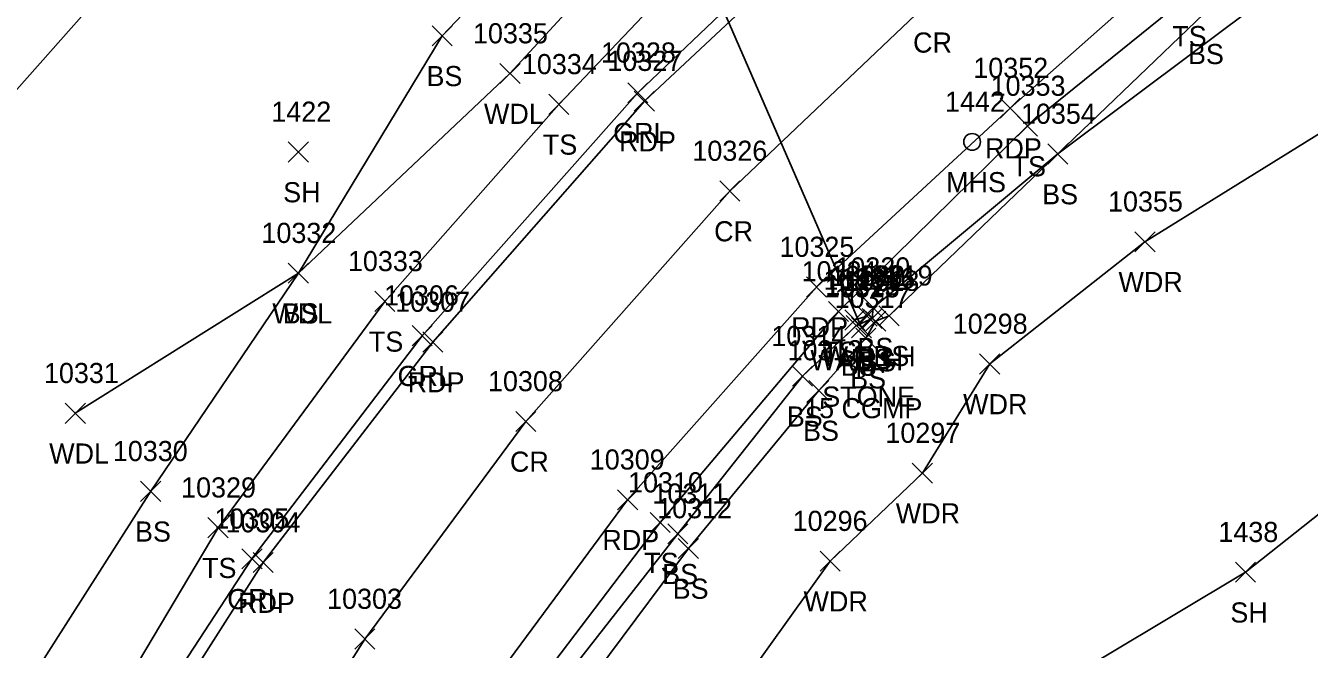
# Model space of a CAD drawing. Extents: x 1651685 to 1653558, y 889533 to 891085.
# Drawn here: x 1652813.1 to 1652940.5, y 890590.1 to 890652 of the extents above; entities that cross this region are included whole.
import ezdxf

# ---------------------------------------------------------------- set-up
doc = ezdxf.new("R2010")
doc.units = 0
for name, color, linetype in [('D_A', 7, 'Continuous'), ('D_C', 7, 'Continuous'), ('D_I', 7, 'Continuous'), ('D_TIC', 7, 'Continuous'), ('DCP', 7, 'Continuous'), ('DHW', 7, 'Continuous'), ('L_A', 7, 'Continuous'), ('L_I', 7, 'Continuous'), ('L_TIC', 7, 'Continuous'), ('LAWA', 7, 'Continuous'), ('LELB', 7, 'Continuous'), ('LSOGP', 7, 'Continuous'), ('P_A', 7, 'Continuous'), ('P_I', 7, 'Continuous'), ('P_TIC', 7, 'Continuous'), ('PET', 7, 'Continuous'), ('PRC', 7, 'Continuous'), ('R_A', 7, 'Continuous'), ('R_I', 7, 'Continuous'), ('R_TIC', 7, 'Continuous'), ('RGR', 7, 'Continuous'), ('U_A', 7, 'Continuous'), ('U_I', 7, 'Continuous'), ('USMH', 7, 'Continuous')]:
    doc.layers.add(name, color=color, linetype=linetype)

msp = doc.modelspace()

# ---------------------------------------------------------------- linework, layer by layer
at = {"layer": 'D_TIC'}
for points in [[(1652895.63, 890622.2), (1652897.63, 890624.2)], [(1652897.63, 890622.2), (1652895.63, 890624.2)], [(1652894.4, 890621.81), (1652896.4, 890623.81)], [(1652896.4, 890621.81), (1652894.4, 890623.81)], [(1652895.07, 890621.05), (1652897.07, 890623.05)], [(1652897.07, 890621.05), (1652895.07, 890623.05)]]:
    msp.add_lwpolyline(points, dxfattribs=at)
at = {"layer": 'DCP'}
msp.add_lwpolyline([(1652896.07, 890622.05), (1652875.51, 890669.35)], dxfattribs=at)
at = {"layer": 'DHW'}
msp.add_lwpolyline([(1652895.4, 890622.81), (1652896.63, 890623.2)], dxfattribs=at)
at = {"layer": 'L_TIC'}
for points in [[(1652853.42, 890650.04), (1652855.42, 890652.04)], [(1652855.42, 890650.04), (1652853.42, 890652.04)], [(1652860.15, 890646.29), (1652862.15, 890648.29)], [(1652862.15, 890646.29), (1652860.15, 890648.29)], [(1652865.01, 890643.23), (1652867.01, 890645.23)], [(1652867.01, 890643.23), (1652865.01, 890645.23)], [(1652911.56, 890641.08), (1652913.56, 890643.08)], [(1652913.56, 890641.08), (1652911.56, 890643.08)], [(1652839.14, 890638.5), (1652841.14, 890640.5)], [(1652841.14, 890638.5), (1652839.14, 890640.5)], [(1652914.57, 890638.3), (1652916.57, 890640.3)], [(1652916.57, 890638.3), (1652914.57, 890640.3)], [(1652914.57, 890638.3), (1652916.57, 890640.3)], [(1652916.57, 890638.3), (1652914.57, 890640.3)], [(1652923.22, 890629.58), (1652925.22, 890631.58)], [(1652925.22, 890629.58), (1652923.22, 890631.58)], [(1652839.14, 890626.46), (1652841.14, 890628.46)], [(1652841.14, 890626.46), (1652839.14, 890628.46)], [(1652839.14, 890626.46), (1652841.14, 890628.46)], [(1652841.14, 890626.46), (1652839.14, 890628.46)], [(1652847.73, 890623.66), (1652849.73, 890625.66)], [(1652849.73, 890623.66), (1652847.73, 890625.66)], [(1652892.78, 890622.65), (1652894.78, 890624.65)], [(1652894.78, 890622.65), (1652892.78, 890624.65)], [(1652896.22, 890623.03), (1652898.22, 890625.03)], [(1652898.22, 890623.03), (1652896.22, 890625.03)], [(1652897.8, 890622.23), (1652899.8, 890624.23)], [(1652899.8, 890622.23), (1652897.8, 890624.23)], [(1652894.56, 890621.27), (1652896.56, 890623.27)], [(1652896.56, 890621.27), (1652894.56, 890623.27)], [(1652896.12, 890621.95), (1652898.12, 890623.95)], [(1652898.12, 890621.95), (1652896.12, 890623.95)], [(1652896.47, 890621.7), (1652898.47, 890623.7)], [(1652898.47, 890621.7), (1652896.47, 890623.7)], [(1652895.5, 890620.01), (1652897.5, 890622.01)], [(1652897.5, 890620.01), (1652895.5, 890622.01)], [(1652907.8, 890617.44), (1652909.8, 890619.44)], [(1652909.8, 890617.44), (1652907.8, 890619.44)], [(1652889.21, 890616.22), (1652891.21, 890618.22)], [(1652891.21, 890616.22), (1652889.21, 890618.22)], [(1652890.82, 890614.8), (1652892.82, 890616.8)], [(1652892.82, 890614.8), (1652890.82, 890616.8)], [(1652816.98, 890612.54), (1652818.98, 890614.54)], [(1652818.98, 890612.54), (1652816.98, 890614.54)], [(1652901.11, 890606.6), (1652903.11, 890608.6)], [(1652903.11, 890606.6), (1652901.11, 890608.6)], [(1652824.47, 890604.79), (1652826.47, 890606.79)], [(1652826.47, 890604.79), (1652824.47, 890606.79)], [(1652831.16, 890601.17), (1652833.16, 890603.17)], [(1652833.16, 890601.17), (1652831.16, 890603.17)], [(1652875.07, 890601.68), (1652877.07, 890603.68)], [(1652877.07, 890601.68), (1652875.07, 890603.68)], [(1652876.83, 890600.57), (1652878.83, 890602.57)], [(1652878.83, 890600.57), (1652876.83, 890602.57)], [(1652877.87, 890599.11), (1652879.87, 890601.11)], [(1652879.87, 890599.11), (1652877.87, 890601.11)], [(1652891.95, 890597.85), (1652893.95, 890599.85)], [(1652893.95, 890597.85), (1652891.95, 890599.85)], [(1652933.21, 890596.75), (1652935.21, 890598.75)], [(1652935.21, 890596.75), (1652933.21, 890598.75)]]:
    msp.add_lwpolyline(points, dxfattribs=at)
at = {"layer": 'LAWA'}
for points in [[(1652817.98, 890613.54), (1652840.14, 890627.46), (1652861.15, 890647.29), (1652878.51, 890666.18), (1652884.26, 890671.52), (1652922.69, 890701.4), (1652959.19, 890728.02), (1652986.15, 890746.08), (1653025.9, 890769.89), (1653049.43, 890788.17), (1653075.47, 890803.38), (1653097.52, 890818.66), (1653132.33, 890844.48)], [(1652833.35, 890477.68), (1652833.39, 890492.3), (1652850.18, 890532.6), (1652867.73, 890564.2), (1652876.6, 890576.01), (1652892.95, 890598.85), (1652902.11, 890607.6), (1652908.8, 890618.44), (1652924.22, 890630.58), (1652962.12, 890654.07), (1652988.27, 890674.02), (1653019.66, 890699.72), (1653055.48, 890726.92), (1653095, 890752.3), (1653138.9, 890781.66), (1653162.63, 890798.14), (1653173.84, 890802.86)]]:
    msp.add_lwpolyline(points, dxfattribs=at)
at = {"layer": 'LELB'}
for points in [[(1652773.03, 890464.56), (1652787.9, 890509.35), (1652802.92, 890548.75), (1652814.17, 890571.87), (1652832.16, 890602.17), (1652848.73, 890624.66), (1652866.01, 890644.23), (1652889.12, 890668.57), (1652926.33, 890696.32), (1652964.24, 890723.35), (1652991.22, 890740.2), (1653028.13, 890766.86), (1653057.75, 890784.91), (1653079.01, 890799.53), (1653102.53, 890813.78), (1653139.28, 890840.79)], [(1652801.17, 890441.9), (1652819.95, 890497.78), (1652834.5, 890541.46), (1652846.59, 890562.12), (1652860.39, 890582.03), (1652876.07, 890602.68), (1652893.78, 890623.65), (1652912.56, 890642.08), (1652928.52, 890655.01), (1652947.04, 890668.65), (1652977.97, 890691.06), (1653009.95, 890711.96), (1653047.06, 890737.13), (1653086.67, 890762.46), (1653129.22, 890790.4), (1653161.56, 890810.77), (1653178.09, 890819.36), (1653180.64, 890814.31), (1653173.84, 890802.86)], [(1652803.19, 890441), (1652820.95, 890497.33), (1652835.58, 890541.15), (1652847.79, 890560.97), (1652861.63, 890580.86), (1652877.83, 890601.57), (1652890.21, 890617.22), (1652895.56, 890622.27), (1652897.12, 890622.95), (1652897.22, 890624.03), (1652915.57, 890639.3), (1652930.05, 890653.23), (1652948.11, 890667.03), (1652978.83, 890689.41), (1653011.67, 890709.88), (1653048.76, 890734.73), (1653087.02, 890761.14), (1653131.31, 890788.11), (1653159.98, 890805.73), (1653164.16, 890807.03), (1653164.17, 890807.66), (1653169.82, 890813.7), (1653178.09, 890819.36)], [(1652803.19, 890441), (1652822.35, 890480.19), (1652822.96, 890495.87), (1652838.19, 890539.83), (1652849.62, 890560.27), (1652863.19, 890579.04), (1652878.87, 890600.11), (1652891.82, 890615.8), (1652896.5, 890621.01), (1652897.47, 890622.7), (1652898.8, 890623.23), (1652915.57, 890639.3), (1652950.1, 890665.22), (1652980.52, 890686.66), (1653013.67, 890707.26), (1653050.87, 890733.01), (1653089.27, 890757.95), (1653133.42, 890785.98), (1653160.95, 890802.08), (1653164.63, 890804.85), (1653167.22, 890806.35), (1653170.81, 890811.17), (1653178.09, 890819.36)], [(1652740.63, 890407.57), (1652746.83, 890413.23), (1652755.32, 890445.88), (1652760.35, 890468.2), (1652780.77, 890512.23), (1652796.45, 890551.5), (1652807.59, 890577.74), (1652825.47, 890605.79), (1652840.14, 890627.46), (1652854.42, 890651.04), (1652870.71, 890668.15), (1652876.32, 890668.87), (1652880.71, 890674.05), (1652916.29, 890707.34), (1652954.78, 890736.09), (1652983.82, 890751.78), (1653022.66, 890774.83), (1653049.43, 890788.17)]]:
    msp.add_lwpolyline(points, dxfattribs=at)
at = {"layer": 'LSOGP'}
for points in [[(1653191.35, 890868.11), (1653139.25, 890847.21), (1653133.81, 890854.84), (1653132.26, 890853.62), (1653128.23, 890850.65), (1653088.88, 890824.36), (1653067.93, 890808.39), (1653036.42, 890796.38), (1653023.39, 890789.29), (1652975.72, 890758.11), (1652938.51, 890752.73), (1652900.6, 890736.09), (1652902.13, 890723.86), (1652868.79, 890705.34), (1652839.11, 890687.76), (1652822.21, 890657.08), (1652787.43, 890617.81), (1652783.5, 890592.65), (1652777.63, 890568.95), (1652768.73, 890549.07), (1652760.18, 890544.48), (1652755.23, 890514.52), (1652738.16, 890487.37)], [(1652860.84, 890470.43), (1652866.91, 890496.63), (1652876.03, 890531.03), (1652888.38, 890556.27), (1652912.99, 890585.04), (1652934.21, 890597.75), (1652965.72, 890622.73), (1652993.55, 890638.61), (1652995.94, 890655.58), (1652988.27, 890674.02), (1653019.66, 890699.72), (1653059.51, 890723.89), (1653095, 890752.3), (1653138.9, 890781.66), (1653162.63, 890798.14), (1653173.85, 890802.86), (1653182.19, 890805.28), (1653198.8, 890815.08)]]:
    msp.add_lwpolyline(points, dxfattribs=at)
at = {"layer": 'P_TIC'}
for points in [[(1652873.5, 890643.55), (1652875.5, 890645.55)], [(1652875.5, 890643.55), (1652873.5, 890645.55)], [(1652909.84, 890642.86), (1652911.84, 890644.86)], [(1652911.84, 890642.86), (1652909.84, 890644.86)], [(1652881.99, 890634.62), (1652883.99, 890636.62)], [(1652883.99, 890634.62), (1652881.99, 890636.62)], [(1652890.59, 890625.08), (1652892.59, 890627.08)], [(1652892.59, 890625.08), (1652890.59, 890627.08)], [(1652852.5, 890619.62), (1652854.5, 890621.62)], [(1652854.5, 890619.62), (1652852.5, 890621.62)], [(1652861.72, 890611.73), (1652863.72, 890613.73)], [(1652863.72, 890611.73), (1652861.72, 890613.73)], [(1652871.84, 890603.95), (1652873.84, 890605.95)], [(1652873.84, 890603.95), (1652871.84, 890605.95)], [(1652835.65, 890597.71), (1652837.65, 890599.71)], [(1652837.65, 890597.71), (1652835.65, 890599.71)], [(1652845.73, 890590.11), (1652847.73, 890592.11)], [(1652847.73, 890590.11), (1652845.73, 890592.11)]]:
    msp.add_lwpolyline(points, dxfattribs=at)
at = {"layer": 'PET'}
for points in [[(1652776.68, 890458.63), (1652791.9, 890507.53), (1652801.72, 890533.82), (1652810.09, 890553.36), (1652823.07, 890577.38), (1652836.65, 890598.71), (1652853.5, 890620.62), (1652874.5, 890644.55), (1652894.69, 890663.43), (1652909.83, 890677.02), (1652929.28, 890691.96), (1652967.44, 890717.98), (1652993.7, 890736.14), (1653032.31, 890761.89), (1653070.4, 890786.93), (1653112.15, 890813.99), (1653148.48, 890837.47), (1653192.87, 890865.71), (1653235.94, 890893.09), (1653280.18, 890921.16), (1653320.29, 890946.68)], [(1652797.7, 890444.76), (1652815.98, 890499.36), (1652826.44, 890526.94), (1652833.17, 890541.97), (1652844.38, 890563.93), (1652857.27, 890583.87), (1652872.84, 890604.95), (1652891.59, 890626.08), (1652910.84, 890643.86), (1652926.01, 890657.3), (1652944.49, 890672.05), (1652975.79, 890694.46), (1653007.52, 890715.91), (1653044.82, 890740.95), (1653083.79, 890766.34), (1653126.92, 890794.39), (1653162.42, 890817.19), (1653177.23, 890826.53), (1653212.82, 890849.27), (1653251.6, 890873.99), (1653294.22, 890900.69), (1653334.65, 890925.85)]]:
    msp.add_lwpolyline(points, dxfattribs=at)
at = {"layer": 'PRC'}
msp.add_lwpolyline([(1652786.21, 890448.94), (1652804.54, 890503.78), (1652815.08, 890532.72), (1652822.08, 890547.99), (1652834.04, 890571.05), (1652846.73, 890591.11), (1652862.72, 890612.73), (1652882.99, 890635.62), (1652902.76, 890654.37), (1652917.73, 890667.19), (1652936.47, 890681.71), (1652967.99, 890703.84), (1653000.43, 890726.04), (1653038.85, 890751.54), (1653077.14, 890776.73), (1653119.4, 890804.03), (1653156.21, 890827.39), (1653198.86, 890855.33), (1653243.54, 890883.44), (1653287.35, 890911.24), (1653327.74, 890936.2)], dxfattribs=at)
at = {"layer": 'R_TIC'}
for points in [[(1652872.86, 890644.38), (1652874.86, 890646.38)], [(1652874.86, 890644.38), (1652872.86, 890646.38)], [(1652851.44, 890620.25), (1652853.44, 890622.25)], [(1652853.44, 890620.25), (1652851.44, 890622.25)], [(1652834.53, 890598.08), (1652836.53, 890600.08)], [(1652836.53, 890598.08), (1652834.53, 890600.08)]]:
    msp.add_lwpolyline(points, dxfattribs=at)
at = {"layer": 'RGR'}
msp.add_lwpolyline([(1652753.62, 890407.5), (1652763.75, 890431.04), (1652774.48, 890459.79), (1652790.93, 890508.17), (1652800.51, 890534.29), (1652809.1, 890554.07), (1652821.88, 890578.18), (1652835.53, 890599.08), (1652852.44, 890621.25), (1652873.86, 890645.38), (1652894.3, 890664.88), (1652909.53, 890677.55), (1652928.71, 890692.69), (1652967.13, 890720.62), (1652991.99, 890738.03), (1653030.5, 890764.27), (1653069.01, 890789.08), (1653110.73, 890816.31), (1653147.12, 890839.54), (1653191.34, 890868.1), (1653234.07, 890895.44), (1653279.07, 890923.79), (1653318.83, 890948.74)], dxfattribs=at)
at = {"layer": 'USMH'}
for p, q in [((1652907.05, 890640.5), (1652907.05, 890640.5)), ((1652907.88, 890640.5), (1652907.88, 890640.5))]:
    msp.add_line(p, q, dxfattribs=at)
msp.add_circle((1652907.05, 890640.5), 0.833, dxfattribs=at)

# ---------------------------------------------------------------- texts
at = {"layer": 'D_A'}
for s, p in [('WALLH', (1652890.99, 890617.81)), ('WALLH', (1652892.22, 890618.2)), ('P', (1652895.45, 890617.05))]:
    msp.add_text(s, height=2, dxfattribs=at).set_placement(p)
at = {"layer": 'D_C'}
for s, p in [('STONE', (1652892.17, 890614.2)), ('15 CGMP', (1652890.37, 890613.05))]:
    msp.add_text(s, height=2, dxfattribs=at).set_placement(p)
at = {"layer": 'D_I'}
for s, p in [('10322', (1652892.96, 890626.2)), ('10321', (1652892.29, 890625.81)), ('10323', (1652892.41, 890625.05))]:
    msp.add_text(s, height=2, dxfattribs=at).set_placement(p)
at = {"layer": 'L_A'}
for s, p in [('TS', (1652926.93, 890650.01)), ('BS', (1652928.49, 890648.23)), ('BS', (1652852.86, 890646.04)), ('WDL', (1652858.57, 890642.29)), ('TS', (1652864.42, 890639.23)), ('TS', (1652910.97, 890637.08)), ('SH', (1652838.63, 890634.5)), ('BS', (1652914.01, 890634.3)), ('BS', (1652914.01, 890634.3)), ('WDR', (1652921.59, 890625.58)), ('WDL', (1652837.55, 890622.46)), ('BS', (1652838.58, 890622.46)), ('TS', (1652847.14, 890619.66)), ('TS', (1652892.19, 890618.65)), ('BS', (1652895.66, 890619.03)), ('BS', (1652894, 890617.27)), ('BS', (1652895.56, 890617.95)), ('BS', (1652895.91, 890617.7)), ('BS', (1652897.25, 890618.23)), ('BS', (1652894.94, 890616.01)), ('WDR', (1652906.16, 890613.44)), ('BS', (1652888.65, 890612.22)), ('BS', (1652890.26, 890610.8)), ('WDL', (1652815.39, 890608.54)), ('WDR', (1652899.47, 890602.6)), ('BS', (1652823.91, 890600.79)), ('TS', (1652830.57, 890597.17)), ('TS', (1652874.48, 890597.68)), ('BS', (1652876.27, 890596.57)), ('BS', (1652877.31, 890595.11)), ('WDR', (1652890.31, 890593.85)), ('SH', (1652932.7, 890592.75))]:
    msp.add_text(s, height=2, dxfattribs=at).set_placement(p)
at = {"layer": 'L_I'}
for s, p in [('10335', (1652857.48, 890650.29)), ('10334', (1652862.34, 890647.23)), ('10353', (1652908.89, 890645.08)), ('1422', (1652837.45, 890642.5)), ('10354', (1652911.9, 890642.3)), ('10354', (1652911.9, 890642.3)), ('10355', (1652920.55, 890633.58)), ('10332', (1652836.47, 890630.46)), ('10332', (1652836.47, 890630.46)), ('10333', (1652845.06, 890627.66)), ('10324', (1652890.12, 890626.65)), ('10320', (1652893.47, 890627.03)), ('10316', (1652893.96, 890625.95)), ('10319', (1652895.69, 890626.23)), ('10315', (1652892.46, 890625.27)), ('10318', (1652894.37, 890625.7)), ('10317', (1652893.4, 890624.01)), ('10298', (1652905.13, 890621.44)), ('10314', (1652887.11, 890620.22)), ('10313', (1652888.72, 890618.8)), ('10331', (1652814.87, 890616.54)), ('10297', (1652898.44, 890610.6)), ('10330', (1652821.71, 890608.79)), ('10310', (1652872.88, 890605.68)), ('10329', (1652828.49, 890605.17)), ('10311', (1652875.3, 890604.57)), ('10312', (1652875.77, 890603.11)), ('10296', (1652889.23, 890601.85)), ('1438', (1652931.51, 890600.75))]:
    msp.add_text(s, height=2, dxfattribs=at).set_placement(p)
at = {"layer": 'P_A'}
for s, p in [('CR', (1652901.19, 890649.37)), ('RDP', (1652871.99, 890639.55)), ('RDP', (1652908.33, 890638.86)), ('CR', (1652881.43, 890630.62)), ('RDP', (1652889.08, 890621.08)), ('RDP', (1652850.99, 890615.62)), ('CR', (1652861.15, 890607.73)), ('RDP', (1652870.33, 890599.95)), ('RDP', (1652834.14, 890593.71))]:
    msp.add_text(s, height=2, dxfattribs=at).set_placement(p)
at = {"layer": 'P_I'}
for s, p in [('10327', (1652870.83, 890647.55)), ('10352', (1652907.17, 890646.86)), ('10326', (1652879.27, 890638.62)), ('10325', (1652887.92, 890629.08)), ('10307', (1652849.75, 890623.62)), ('10308', (1652858.97, 890615.73)), ('10309', (1652869.08, 890607.95)), ('10304', (1652832.9, 890601.71)), ('10303', (1652842.99, 890594.11))]:
    msp.add_text(s, height=2, dxfattribs=at).set_placement(p)
at = {"layer": 'R_A'}
for p in [(1652871.4, 890640.38), (1652849.99, 890616.25), (1652833.08, 890594.08)]:
    msp.add_text('GRL', height=2, dxfattribs=at).set_placement(p)
at = {"layer": 'R_I'}
for s, p in [('10328', (1652870.19, 890648.38)), ('10306', (1652848.64, 890624.25)), ('10305', (1652831.79, 890602.08))]:
    msp.add_text(s, height=2, dxfattribs=at).set_placement(p)
at = {"layer": 'U_A'}
msp.add_text('MHS', height=2, dxfattribs=at).set_placement((1652904.47, 890635.5))
at = {"layer": 'U_I'}
msp.add_text('1442', height=2, dxfattribs=at).set_placement((1652904.36, 890643.5))

doc.saveas('drawing.dxf')
